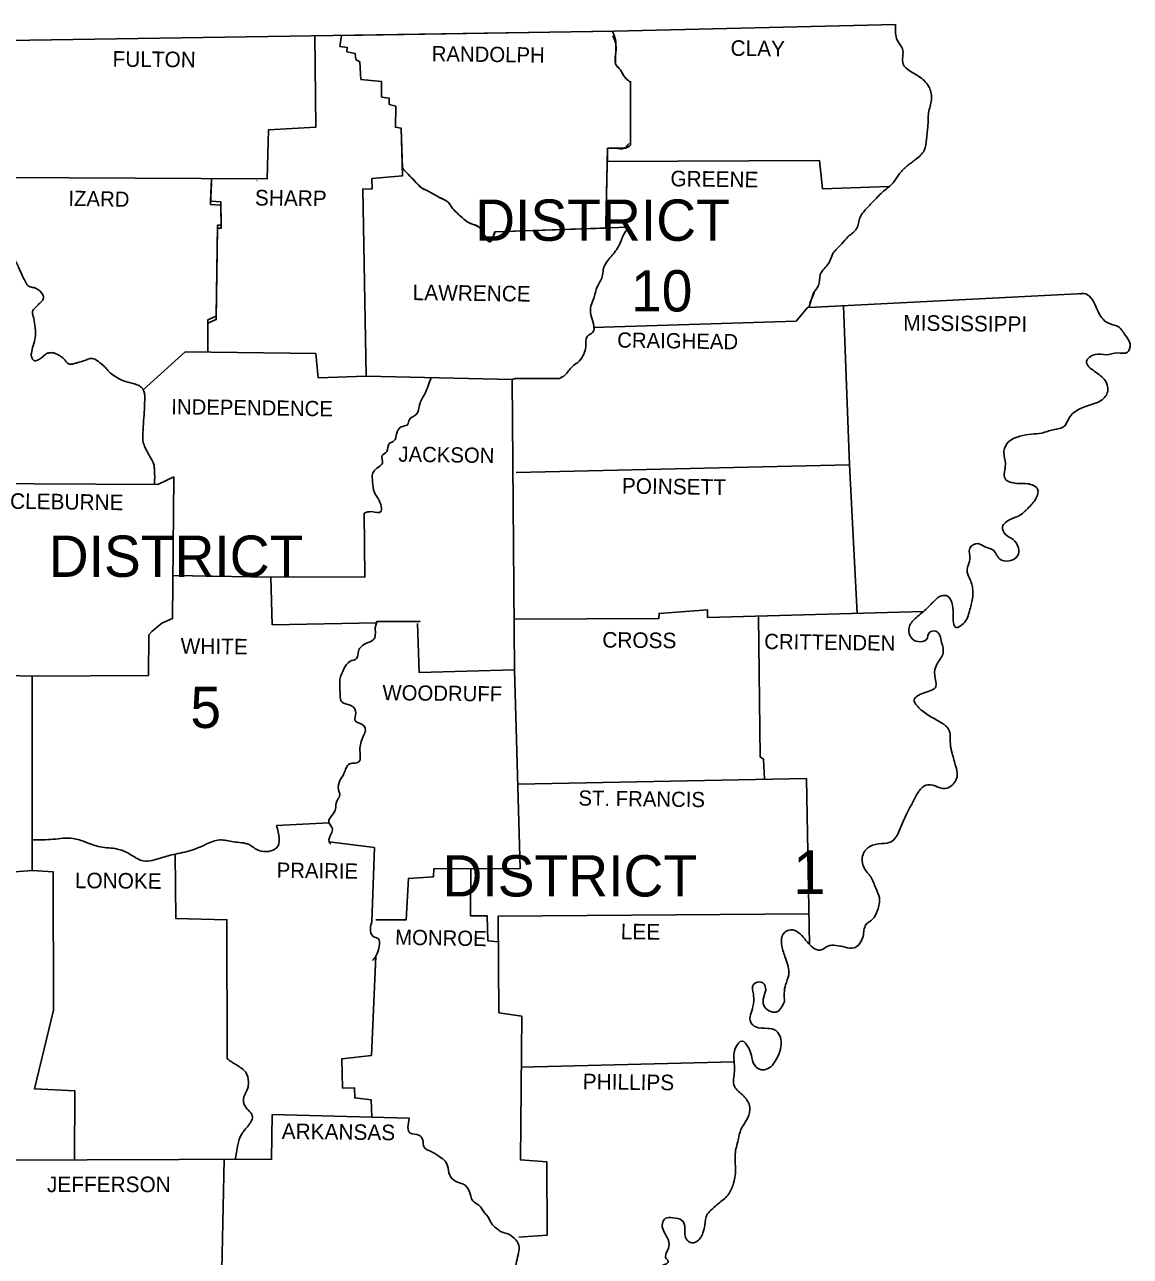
# Model space of a CAD drawing. Extents: x 3046 to 131673, y -8885 to 10756.
# Drawn here: x 66781 to 69768, y 7032 to 10358 of the extents above; entities that cross this region are included whole.
import ezdxf

# ---------------------------------------------------------------- set-up
doc = ezdxf.new("R2010")
doc.units = 0
for name, color, linetype in [('1', 7, 'Continuous'), ('2', 7, 'Continuous'), ('3', 7, 'Continuous')]:
    doc.layers.add(name, color=color, linetype=linetype)

msp = doc.modelspace()

# ---------------------------------------------------------------- linework, layer by layer
at = {"layer": '1'}
for p, q in [((67636.5, 10328.9), (68368.7, 10340.3)), ((68417.5, 10202.4), (68417.5, 10032.6)), ((68898.8, 9593.9), (68910.6, 9630.1)), ((68901.8, 9605.6), (68913.5, 9634)), ((67732.6, 8746.6), (67849, 8746.6))]:
    msp.add_line(p, q, dxfattribs=at)
for points in [[(63766.1, 10313), (65348.2, 10312), (66736.6, 10314.9), (68374.4, 10340.4), (69133.7, 10358)], [(67565.2, 10327.8), (67567.2, 10081.1), (67440, 10074.3), (67436.1, 9941.2), (66723.5, 9945.1)], [(67801.4, 9970.4), (67798.1, 10078.2), (67782.5, 10081.1), (67783.5, 10137.9), (67765.9, 10142.7), (67765.9, 10159.4), (67745.3, 10162.3), (67745.3, 10204.4), (67689.5, 10210.3), (67686.6, 10257.2), (67675.8, 10264.1), (67673.9, 10279.7), (67651.4, 10284.6), (67652.4, 10296.4), (67632.8, 10299.3), (67636.5, 10328.9)], [(67635.7, 10322.8), (67632.8, 10299.3), (67652.4, 10296.4), (67651.4, 10284.6), (67673.9, 10279.7), (67675.8, 10264.1), (67686.6, 10257.2), (67689.5, 10210.3), (67745.3, 10204.4), (67745.3, 10162.3), (67765.9, 10159.4), (67765.9, 10142.7), (67783.5, 10137.9), (67782.5, 10081.1), (67798.1, 10078.2), (67802.1, 9950), (67718.9, 9942.2), (67719.9, 9914.8), (67694.4, 9913.8), (67703.2, 9408.9), (68097.5, 9400.1), (68104.4, 8615.5), (67847.1, 8608.6), (67842.2, 8740.7)], [(66736.6, 10309.1), (66738.5, 10076.2), (66721.9, 10075.2), (66724.8, 9831.6), (66656.3, 9821.8), (66662.2, 9756.3), (66685.7, 9725.9), (66683.7, 9648.7), (66550.7, 9643.8), (66545.8, 9524.4), (66424.5, 9520.5), (66418.6, 9375.7), (66425.4, 9363.9), (66428.4, 9133), (66637.7, 9119.3), (66634.8, 8603.7), (66801.1, 8598.8), (66801.1, 8074.4), (66670, 8064.6), (66660.3, 7949.2), (66440.1, 7948.2)], [(68417.5, 10205.4), (68417.5, 10040)], [(68355.8, 10024.4), (68350.7, 9808.8), (68051.5, 9798.3)], [(68350.9, 9819.9), (68355.8, 10024.4), (68355.8, 9988.2), (68928.2, 9991.1), (68936, 9914.8), (69115.6, 9921.3)], [(67285.6, 9942), (67283.5, 9881.5), (67310.9, 9879.6), (67311.9, 9816.9), (67302.1, 9816.9), (67298.2, 9570.4), (67275.7, 9560.6), (67275.7, 9478.4)], [(67285.5, 9929.5), (67283.5, 9872.7), (67310.9, 9870.7), (67311.9, 9808.1), (67302.1, 9808.1), (67298.2, 9561.6), (67275.7, 9551.8), (67275.7, 9473.7)], [(67407.8, 9936.3), (67408.7, 9937.3)], [(68051.5, 9798.3), (68412.2, 9811)], [(68898.8, 9593.9), (69641.5, 9632)], [(68316.8, 9539.9), (68864.6, 9557.7), (68896.9, 9594.8)], [(68992.5, 9598.7), (69009.4, 9169.2), (69029.3, 8768.4)], [(67101.4, 9371.9), (67215, 9474.5), (67567.2, 9469.6), (67574.1, 9404), (67703.2, 9409)], [(68225.7, 9402.1), (68106.3, 9402.1), (68097.5, 9400.1)], [(69009.4, 9169.2), (68108.3, 9148.7)], [(66637.7, 9119.3), (67140.6, 9116.4), (67183.7, 9136.9), (67180.8, 8754.4), (67151.4, 8741.7), (67125, 8719.2), (67116.2, 8710.4), (67115.2, 8600.8), (66801.1, 8598.8)], [(67698.3, 9039.1), (67700.3, 8866.9), (67445.9, 8865.9), (67181.7, 8870.9)], [(67445.9, 8865.9), (67449.8, 8737.8), (67731.5, 8742.8)], [(68103.2, 8752.4), (68493.8, 8754.4), (68494.8, 8768.1), (68625.9, 8777.9), (68625.9, 8757.3), (69208.7, 8773.3)], [(68762.8, 8761.1), (68767.7, 8380.6), (68776.5, 8374.8), (68779.7, 8320.6)], [(67732.6, 8746.6), (67727.7, 8728.9)], [(68104.4, 8615.5), (68119.1, 8079.3), (67886.2, 8078.3), (67885.2, 8056.8), (67817.7, 8052.9), (67811.8, 7941.3), (67729.7, 7941.3)], [(68112.8, 8307.2), (68893, 8322.9)], [(68893, 8322.9), (68901.2, 7874.7)], [(67461.6, 8195.7), (67603.4, 8202.6)], [(67603.4, 8151.7), (67725.7, 8136), (67718.9, 7936.4)], [(67187.6, 8119.4), (67189.6, 7944.3), (67327.5, 7941.3), (67328.5, 7565.6)], [(66801.1, 8074.4), (66857.9, 8070.5), (66858.9, 7696.7), (66808, 7484.4), (66916.6, 7479.5), (66915.6, 7292.5)], [(67986, 8078.7), (67985, 7952.1), (68030, 7952.1), (68032, 7884.6), (68060.9, 7881.6)], [(68116.1, 7084.2), (68192.4, 7089.1), (68191.5, 7287.8), (68120, 7292.6), (68123.9, 7681.1), (68062.3, 7689.9), (68060.4, 7951.1), (68899.7, 7957)], [(67729.7, 7842.5), (67717.9, 7574.4), (67637.7, 7565.6), (67639.6, 7486.4), (67671.9, 7487.3), (67672.9, 7460), (67716.9, 7455.1), (67718.4, 7407.8)], [(68122.6, 7543), (68697.4, 7557.3)], [(67819.7, 7405.2), (67449.8, 7414.9), (67447.9, 7294.6), (66699.4, 7291.7)], [(67319.8, 7294.1), (67311.9, 6910.1), (67447.9, 6899.3)]]:
    msp.add_lwpolyline(points, dxfattribs=at)
for points in [[(69133.7, 10358), (69138.6, 10314.9), (69152.3, 10292.4), (69154.2, 10251.3), (69170.8, 10233.7), (69199.2, 10216.1), (69224.7, 10187.8), (69230.5, 10154.5), (69222.7, 10120.2), (69220.7, 10082.1), (69216.8, 10048.8), (69211, 10018.5), (69187.5, 9994), (69165, 9976.4), (69144.4, 9955.9), (69129.8, 9934.3), (69104.3, 9910.9), (69078.9, 9886.4), (69058.3, 9864.9), (69037.8, 9837.5), (69028, 9807.2), (69005.5, 9785.6), (68987.9, 9766.1), (68964.4, 9739.6), (68952.7, 9713.2), (68930.2, 9682.9), (68925.3, 9653.5), (68910.6, 9630.1), (68909.6, 9626.1)], [(68368.7, 10340.3), (68370.6, 10335.8), (68372.5, 10331.2), (68375.5, 10322), (68377.6, 10312.6), (68377.9, 10310.3), (68378.1, 10307.9), (68378.3, 10303.2), (68378.2, 10296.6), (68377.9, 10290), (68377.6, 10283.4), (68377.4, 10276.8), (68377.2, 10273.7), (68376.7, 10264.6), (68376.7, 10258.4), (68376.9, 10255.4), (68377.1, 10253.9), (68377.2, 10253.1), (68377.4, 10252.3), (68378.1, 10249.9), (68378.7, 10248.7), (68379.4, 10247.6), (68381, 10245.5), (68382.8, 10243.6), (68386.7, 10239.7), (68388.5, 10237.8), (68390.1, 10235.7), (68393.2, 10230.6), (68396.3, 10225.4), (68399.4, 10220.2), (68401, 10217.6), (68402.8, 10215.1), (68404.9, 10212.7), (68407.3, 10210.4), (68409.9, 10208.4), (68417.5, 10202.4)], [(68369.5, 10327.7), (68378.3, 10303.2), (68377.4, 10276.8), (68377.4, 10252.3), (68390.1, 10235.7), (68402.8, 10215.1), (68412.6, 10206.3)], [(68413.6, 10037.1), (68400.8, 10024.4), (68376.4, 10024.4), (68355.8, 10024.4)], [(68417.5, 10032.6), (68415.7, 10030.9), (68413.8, 10029.3), (68409.7, 10026.7), (68405.4, 10025), (68403.1, 10024.5), (68402, 10024.4), (68400.8, 10024.4), (68376.4, 10024.4), (68355.8, 10024.4)], [(68051.5, 9798.3), (68050.1, 9794.1), (68048.4, 9789.2), (68044.5, 9779.4), (68040.3, 9772.4), (68038.1, 9771.1), (68037, 9771.2), (68035.9, 9771.9), (68035.4, 9772.4), (68035, 9772.8), (68034.1, 9773.8), (68032.2, 9776), (68028.6, 9781.2), (68024.9, 9786.9), (68023, 9789.8), (68021.2, 9792.5), (68018.5, 9796.7), (68016, 9800.9), (68013.3, 9805.1), (68010.5, 9809.1), (68007.3, 9812.2), (68003.6, 9814.5), (67995.1, 9817.8), (67986.2, 9820.6), (67978.2, 9824.8), (67972.9, 9828.7), (67967.7, 9832.8), (67962.6, 9837), (67957.6, 9841.4), (67947.2, 9851.5), (67937.1, 9861.9), (67935.2, 9864.2), (67933.4, 9866.6), (67930.2, 9871.7), (67926.7, 9876.5), (67922.4, 9880.5), (67921.1, 9881.4), (67919.7, 9882.2), (67911.2, 9886.6), (67905.5, 9889.3), (67899.9, 9892.3), (67887.2, 9899.6), (67874.5, 9906.9), (67869, 9909.6), (67863.4, 9911.9), (67857.9, 9914.4), (67852.9, 9917.7), (67851.7, 9918.8), (67850.4, 9919.9), (67848, 9922.1), (67843.4, 9926.8), (67834.3, 9936.3), (67817.8, 9953.2), (67801.4, 9970.4)], [(67812.8, 9958.8), (67834.3, 9936.3), (67852.9, 9917.7), (67874.5, 9906.9), (67899.9, 9892.3), (67922.4, 9880.5), (67937.1, 9861.9), (67957.6, 9841.4), (67978.2, 9824.8), (68010.5, 9809.1), (68021.2, 9792.5), (68035.9, 9771.9), (68051.5, 9798.3)], [(68412.2, 9811), (68396.9, 9786.6), (68385.2, 9759.2), (68361.7, 9727.9), (68344.1, 9697.6), (68341.2, 9677), (68327.5, 9649.6), (68319.6, 9622.2), (68310.8, 9598.8), (68310.8, 9574.3), (68317.7, 9549.8), (68315.7, 9527.3), (68301, 9516.6), (68297.1, 9488.2), (68291.3, 9468.6), (68278.5, 9449.1), (68259.9, 9434.4), (68240.4, 9411.9), (68225.7, 9402.1)], [(66685.7, 9725.9), (66695.3, 9722.3), (66705.1, 9720.3), (66715, 9719.5), (66724.8, 9719.1), (66730.9, 9721.1), (66737, 9725.5), (66742.8, 9728.9), (66745.6, 9729.2), (66748.3, 9727.9), (66753.9, 9722.3), (66758.2, 9716), (66761.7, 9709.3), (66764.9, 9702.5), (66773.7, 9682.9), (66780.5, 9668.5), (66784.3, 9661.4), (66786.3, 9657.9), (66788.4, 9654.5), (66793, 9650.8), (66799.2, 9649.2), (66805.8, 9648), (66809, 9647.1), (66811.9, 9645.7), (66829.5, 9630.1), (66832, 9621.6), (66831.4, 9617.2), (66829.5, 9613.4), (66825.8, 9609.4), (66821.8, 9605.6), (66817.7, 9601.8), (66813.9, 9597.8), (66812.1, 9595.9), (66806.5, 9590.4), (66803.5, 9586.5), (66802.6, 9584.4), (66802.1, 9582.1), (66802.4, 9577.5), (66803.5, 9572.9), (66804.9, 9568.2), (66806, 9563.5), (66808.1, 9550.8), (66809.9, 9538.1), (66809.9, 9513.6), (66804.1, 9491.1), (66799.2, 9470.6), (66798.7, 9466.1), (66799.3, 9461.7), (66801.1, 9457.3), (66802.4, 9455.1), (66804.1, 9453), (66806.1, 9451.3), (66808.3, 9450.5), (66813.3, 9451.2), (66822.7, 9455.9), (66827.6, 9459.4), (66832.2, 9463.6), (66837, 9467.7), (66842.2, 9470.6), (66847.2, 9471.8), (66852.5, 9472.3), (66862.8, 9470.6), (66872.8, 9465.7), (66882.4, 9459.8), (66887.6, 9454.9), (66892.2, 9449), (66897.1, 9443.8), (66899.8, 9442.1), (66901.3, 9441.5), (66902.9, 9441.2), (66913.1, 9442.2), (66923.4, 9445.1), (66940.1, 9450), (66963.6, 9456.9), (66980.2, 9448.1), (66994.9, 9436.3), (66999.4, 9431.8), (67003.6, 9427), (67007.9, 9422.2), (67012.5, 9417.7), (67029.1, 9406), (67050.6, 9395.2), (67057.1, 9393.1), (67063.7, 9391.7), (67070.4, 9390.3), (67077.1, 9388.4), (67090.9, 9382.4), (67096.9, 9377.9), (67099.4, 9375.1), (67100.5, 9373.5), (67101.5, 9371.8), (67103.1, 9368.2), (67105.5, 9357.6), (67105.7, 9350.5), (67105.4, 9343.4), (67104.4, 9318.9), (67102.5, 9288.6), (67100.5, 9255.3), (67100.1, 9247.2), (67100.2, 9239.1), (67101.1, 9231), (67102.1, 9227), (67103.5, 9223), (67108.6, 9212), (67114.2, 9201.5), (67121.2, 9189), (67127.9, 9176.1), (67131, 9164.5), (67131.5, 9158.6), (67131.8, 9152.6), (67132.3, 9134.5), (67131, 9116.5)], [(69630.7, 9631), (69641.5, 9632), (69674.7, 9596.8), (69689.4, 9567.4), (69710.9, 9550.8), (69735.4, 9542), (69754, 9519.5), (69766.7, 9495), (69759.8, 9473.5), (69732.4, 9471.6), (69702.1, 9466.7), (69672.8, 9467.6), (69649.3, 9448.1), (69670.8, 9421.7), (69699.2, 9397.2), (69707, 9370.8), (69691.4, 9345.3), (69660, 9331.6), (69629.7, 9319.9), (69602.3, 9296.4), (69589.6, 9273.9), (69559.3, 9264.1), (69528, 9255.3), (69500.6, 9252.4), (69469.3, 9246.5), (69438.9, 9231.8), (69426.2, 9206.4), (69430.1, 9170.2), (69429.1, 9132.1), (69461.4, 9119.3), (69489.8, 9118.4), (69517.2, 9103.7), (69514.3, 9082.2), (69493.7, 9054.8), (69469.3, 9033.2), (69444.8, 9022.5), (69422.3, 9001.9), (69430.1, 8981.4), (69450.7, 8967.7), (69465.3, 8945.2), (69463.4, 8924.6), (69439.9, 8910), (69414.5, 8915.8), (69395.9, 8940.3), (69374.4, 8948.1), (69355.8, 8956.9), (69334.2, 8944.2), (69334.2, 8915.8), (69326.4, 8885.5), (69333.3, 8863), (69342.1, 8831.7), (69341.1, 8808.2), (69333.3, 8774.9), (69316.6, 8740.7), (69297.1, 8729.9), (69289.2, 8767.1), (69285.3, 8797.4), (69273.6, 8815), (69257.9, 8816), (69237.4, 8801.3), (69214.9, 8778.8), (69186.5, 8754.4), (69169.9, 8729.9), (69178.7, 8699.6), (69200.2, 8691.8), (69216.8, 8697.6), (69225.6, 8717.2), (69242.3, 8720.1), (69257.9, 8689.8)], [(67878.8, 9405.1), (67861.7, 9361), (67848, 9331.6), (67839.2, 9306.2), (67820.6, 9291.5), (67814.8, 9277.8), (67798.1, 9272), (67785.4, 9252.4), (67779.5, 9234.8), (67765.9, 9227), (67759, 9205.4), (67746.3, 9193.7), (67747.3, 9174.1), (67732.6, 9160.4), (67720.8, 9144.8), (67720.8, 9123.2), (67725.7, 9094.9), (67735.5, 9078.2), (67744.3, 9056.7), (67743.3, 9043), (67718.9, 9043), (67698.3, 9039.1)], [(67727.7, 8728.9), (67722.8, 8696.7), (67704.2, 8687.9), (67682.7, 8666.3), (67677.8, 8646.8), (67660.2, 8638.9), (67643.6, 8618.4), (67632.8, 8590), (67632.8, 8560.7), (67639.6, 8527.4), (67664.1, 8518.6), (67675.8, 8499), (67673.9, 8478.5), (67697.4, 8464.8), (67701.3, 8453), (67697.4, 8440.3), (67686.6, 8404.1), (67687.6, 8379.7), (67685.6, 8368.9), (67659.2, 8362), (67643.6, 8335.6), (67632.8, 8317), (67628.9, 8292.6), (67631.8, 8275), (67624, 8261.3), (67621, 8240.7), (67611.3, 8223.1), (67602.5, 8206.5), (67612.2, 8186.9), (67609.3, 8173.2), (67603.4, 8151.7), (67608.3, 8144.8)], [(69257.9, 8689.8), (69261.8, 8661.4), (69245.2, 8631.1), (69239.3, 8600.8), (69242.3, 8570.4), (69211, 8553.8), (69183.6, 8534.2), (69199.2, 8510.8), (69228.6, 8489.2), (69257.9, 8472.6), (69276.5, 8456), (69281.4, 8415.9), (69286.3, 8390.4), (69296.1, 8355.2), (69300, 8330.7), (69282.4, 8301.4), (69261.8, 8295.5), (69240.3, 8302.4), (69214.9, 8304.3), (69194.3, 8284.8), (69179.6, 8257.4), (69165, 8230), (69154.2, 8206.5), (69143.4, 8181), (69121.9, 8151.7), (69095.5, 8146.8), (69064.2, 8139), (69045.6, 8117.4), (69048.5, 8081.2), (69066.2, 8056.8), (69079.9, 8026.5), (69089.6, 8000), (69084.7, 7966.8), (69071, 7942.3), (69053.4, 7927.6), (69045.6, 7896.3), (69032.9, 7872.8), (69021.1, 7865), (68997.7, 7867), (68972.2, 7871.9), (68950.7, 7869.9), (68930.2, 7859.1), (68909.6, 7866), (68888.1, 7889.5), (68870.5, 7907.1), (68850.9, 7913.9), (68830.4, 7903.2), (68826.4, 7870.9), (68836.2, 7837.6), (68845, 7792.6), (68836.2, 7765.2), (68833.3, 7720.2)], [(66800.7, 8156.5), (66857.9, 8158.5), (66911.7, 8160.5), (66945.9, 8150.7), (66985.1, 8138), (67031.1, 8132.1), (67063.4, 8119.4), (67101.5, 8099.8), (67150.4, 8108.6), (67188.6, 8118.4), (67238.5, 8131.1), (67270.8, 8144.8), (67308, 8156.6), (67345.1, 8151.7), (67387.2, 8143.9), (67413.6, 8128.2), (67461.6, 8135.1), (67461.6, 8195.7)], [(67718.9, 7936.4), (67715, 7916.9), (67722.8, 7896.3), (67736.5, 7889.5), (67738.5, 7869.9), (67733.6, 7850.3), (67729.7, 7842.5), (67720.8, 7830.8)], [(68833.3, 7720.2), (68810.8, 7691.8), (68777.5, 7709.4), (68777.5, 7732.9), (68782.4, 7757.4), (68770.7, 7773), (68750.1, 7766.2), (68750.1, 7735.9), (68748.2, 7706.5), (68742.3, 7664.4), (68756, 7651.7), (68787.3, 7647.8), (68809.8, 7641.9), (68823.5, 7619.4), (68822.5, 7592), (68811.8, 7565.6), (68796.1, 7544.1), (68771.7, 7536.3), (68752.1, 7549), (68744.3, 7574.4), (68735.5, 7596.9), (68718.8, 7613.6), (68701.2, 7595), (68697.3, 7560.7), (68698.3, 7531.4), (68698.3, 7491.3), (68723.7, 7464.8), (68739.4, 7434.5), (68734.5, 7407.1), (68715.9, 7374.8), (68708.1, 7346.5), (68700.2, 7308.3), (68701.2, 7266.2), (68694.4, 7225.1), (68680.7, 7197.7), (68655.2, 7175.2), (68638.6, 7160.6), (68624.9, 7145.9), (68618, 7116.5), (68613.2, 7096), (68594.6, 7071.5), (68579.9, 7069.6), (68568.1, 7079.4), (68564.2, 7096), (68564.2, 7112.6), (68556.4, 7129.3), (68531.9, 7136.1), (68512.4, 7135.1), (68503.6, 7121.4), (68516.3, 7083.3), (68521.2, 7058.8), (68514.3, 7025.5), (68518.2, 7021.6), (68483, 7003), (68454.7, 7000.1), (68431.2, 6993.3), (68408.7, 6978.6), (68397.9, 6957.1), (68382.2, 6939.4), (68368.6, 6922.8), (68350, 6915), (68329.4, 6918.9), (68302, 6921.8), (68286.4, 6902.3), (68291.3, 6873.9), (68309.8, 6857.3), (68337.2, 6849.4), (68365.6, 6851.4), (68393, 6854.3), (68418.4, 6840.6), (68413.6, 6814.2), (68389.1, 6801.5), (68352.9, 6797.6), (68323.5, 6800.5), (68288.3, 6792.7), (68270.7, 6770.2), (68280.5, 6735.9), (68318.7, 6722.2), (68336.3, 6689.9), (68337.2, 6659.6), (68324.5, 6619.5), (68306.9, 6600.9), (68272.7, 6593.1), (68246.2, 6588.2), (68242.3, 6543.2), (68230.6, 6520.7), (68210, 6513.8), (68180.7, 6528.5), (68163.1, 6535.4), (68141.6, 6545.1), (68114.2, 6561.8), (68093.6, 6558.8), (68099.5, 6515.8), (68101.4, 6513.8), (68124.9, 6481.5), (68148.4, 6456.1), (68159.2, 6425.8)], [(67328.5, 7565.6), (67353, 7549), (67378.4, 7529.4), (67385.3, 7503), (67383.3, 7484.4), (67375.5, 7468.8), (67373.5, 7444.3), (67385.3, 7426.7), (67396, 7412), (67385.3, 7385.6), (67366.7, 7361.1), (67356.9, 7333.7), (67350, 7292.6)], [(67819.7, 7405.2), (67822.6, 7365), (67846.1, 7359.2), (67855.9, 7348.4), (67860.8, 7325.9), (67877.4, 7316.1), (67899.9, 7302.4), (67913.6, 7292.6), (67923.4, 7277), (67929.2, 7251.6), (67944.9, 7234.9), (67966.4, 7227.1), (67982.1, 7208.5), (67991.9, 7182.1), (68007.5, 7170.3), (68023.2, 7149.8), (68031, 7141), (68044.7, 7117.5), (68058.4, 7105.8), (68068.2, 7098.9), (68083.8, 7094), (68103.4, 7081.3), (68116.1, 7061.7), (68116.1, 7047.1), (68111.2, 7024.6), (68107.3, 7001.1), (68105.4, 6974.7), (68103.4, 6951.2), (68112.2, 6931.6), (68107.3, 6902.3), (68097.5, 6886.6), (68096.6, 6865.1), (68093.6, 6832.8), (68089.7, 6814.2), (68080.9, 6783.9), (68068.2, 6768.2)]]:
    msp.add_spline(points, degree=3, dxfattribs=at)

# ---------------------------------------------------------------- texts
msp.add_text('1', height=117.4, dxfattribs=at).set_placement((68856.8, 8010.8))
at = {"layer": '2'}
for s, height, rotation, p in [('CLAY', 42.06, 359.2258, (68687.5, 10273.9)), ('FULTON', 42.06, 359.4996, (67018.3, 10244.5)), ('RANDOLPH', 41.09, 359.2583, (67880.3, 10259.2)), ('GREENE', 42.07, 359.2361, (68525.1, 9921.6)), ('SHARP', 42.06, 359.3905, (67402.9, 9869.8)), ('IZARD', 41.08, 358.9258, (66899, 9868.8)), ('LAWRENCE', 42.07, 359.2678, (67828.9, 9614.2)), ('MISSISSIPPI', 42.062, 359.3097, (69154.2, 9532.2)), ('CRAIGHEAD', 41.09, 359.1159, (68381.3, 9486.2)), ('INDEPENDENCE', 41.081, 359.2187, (67176.9, 9306.2)), ('JACKSON', 41.08, 359.1352, (67790.3, 9178)), ('POINSETT', 42.06, 359.1987, (68394, 9091.9)), ('CLEBURNE', 42.06, 359.2535, (66741.5, 9050.8)), ('CROSS', 42.06, 359.3839, (68341.2, 8676.1)), ('CRITTENDEN', 41.09, 359.213, (68778.5, 8672.2)), ('WHITE', 42.07, 359.3139, (67202.3, 8659.5)), ('WOODRUFF', 41.08, 359.2748, (67747.3, 8534.2)), ('ST. FRANCIS', 41.081, 359.2216, (68276.6, 8249.5)), ('PRAIRIE', 41.09, 359.2116, (67461.6, 8054.8)), ('LONOKE', 42.07, 359.4974, (66916.6, 8026.5)), ('LEE', 42.07, 359.4327, (68391.1, 7888.5)), ('MONROE', 41.08, 359.0331, (67781.5, 7873.8)), ('PHILLIPS', 42.06, 359.3179, (68288.3, 7483.4)), ('ARKANSAS', 42.06, 359.2678, (67475.3, 7349.4))]:
    msp.add_text(s, height=height, rotation=rotation, dxfattribs=at).set_placement(p)
msp.add_text('JEFFERSON', height=42.07, dxfattribs=at).set_placement((66841.3, 7205.6))
at = {"layer": '3'}
for s, height, p in [('DISTRICT', 111.54, (67998, 9774.3)), ('10', 111.54, (68418.8, 9583.5)), ('DISTRICT', 111.54, (66846.1, 8866.9)), ('5', 111.5, (67228.7, 8458.9)), ('DISTRICT', 111.54, (67909.7, 8003.9))]:
    msp.add_text(s, height=height, dxfattribs=at).set_placement(p)

doc.saveas('drawing.dxf')
